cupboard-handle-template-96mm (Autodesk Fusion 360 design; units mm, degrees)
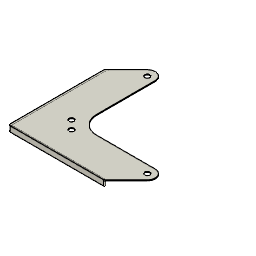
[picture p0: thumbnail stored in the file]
sketch "Sketch1" plane through (0, 0, 0) normal (0, 0, 1) x axis (1, 0, 0)
  line L1 (65, 0) -> (0, 0)
  line L2 (65, 65) -> (65, 0)
  line L3 (0, 65) -> (65, 65)
  line L4 (0, 0) -> (0, 65)
  line L5 (32.5, 43.3333) -> (32.5, 139.3333)
  line L6 (65, 65) -> (0, 0)
  line L7 (-2, -2) -> (0, 0)
  line L8 (-2, 118.9755) -> (-2, -2)
  line L9 (25.4289, 146.4044) -> (-2, 118.9755)
  line L10 (42.5, 65) -> (42.5, 139.3333)
  line L11 (0, 120.9755) -> (0, 65)
  circle C1 centre (32.5, 43.3333) radius 3.15
  circle C2 centre (32.5, 139.3333) radius 3.15
  arc A1 centre (32.5, 139.3333) radius 10 clockwise from (25.4289, 146.4044) to (42.5, 139.3333)
  arc A2 centre (65, 65) radius 22.5 clockwise from (49.0901, 49.0901) to (42.5, 65)
  point P1 (0, 0)
  point P2 (0, 0)
  point P7 (32.5, 139.3333)
  point P8 (32.5, 139.3333)
  point P6 (32.5, 43.3333)
  point P9 (32.5, 43.3333)
  point P10 (0, 0)
  point P15 (32.5, 139.3333)
  point P17 (0, 120.9755)
  point P18 (65, 65)
  point P4 (65, 65)
  point P20 (32.5, 65)
  point P19 (49.0901, 49.0901)
  point P3 (65, 0)
  horizontal L1
  vertical L2
  horizontal L3
  vertical L4
  coincident P1 P2
  equal L2 L3
  coincident P7 P8
  coincident P6 P9
  vertical L5
  coincident P1 P10
  parallel L6 L7
  perpendicular L1 L8
  equal C1 C2
  tangent L9 A1
  perpendicular L3 L10
  tangent A1 L10
  coincident P7 P15
  coincident L9 P17
  perpendicular L3 L11
  coincident L6 P18
  coincident P4 P18
  midpoint L3 P20
  coincident L5 P20
  tangent L10 A2
  coincident L6 P19
  dimension "d1" distance P3 P4 = 65
  dimension "d2" distance P8 P9 = 96
  dimension "d3" diameter C2 = 6.3
  dimension "d4" distance L3 P6 = 21.6667 (= "d1 / 3")
  dimension "d5" radius A1 = 10
  dimension "d7" distance L8 L11 = 2
  dimension "d8" angle L5 L9 = 45
extrude "Extrude1" new body sketch "Sketch1" profile of L4 C1 C2 L6 L7 L8 L9 A1 L10 L11 A2 along normal blind 1
extrude "Extrude2" add sketch "Sketch1" profile of L4 L7 L8 L9 L11 against normal blind 6
mirror "Mirror1" mirrorStitchTolerance 0.1
fillet "Fillet1" radius 2
fillet "Fillet2" radius 1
